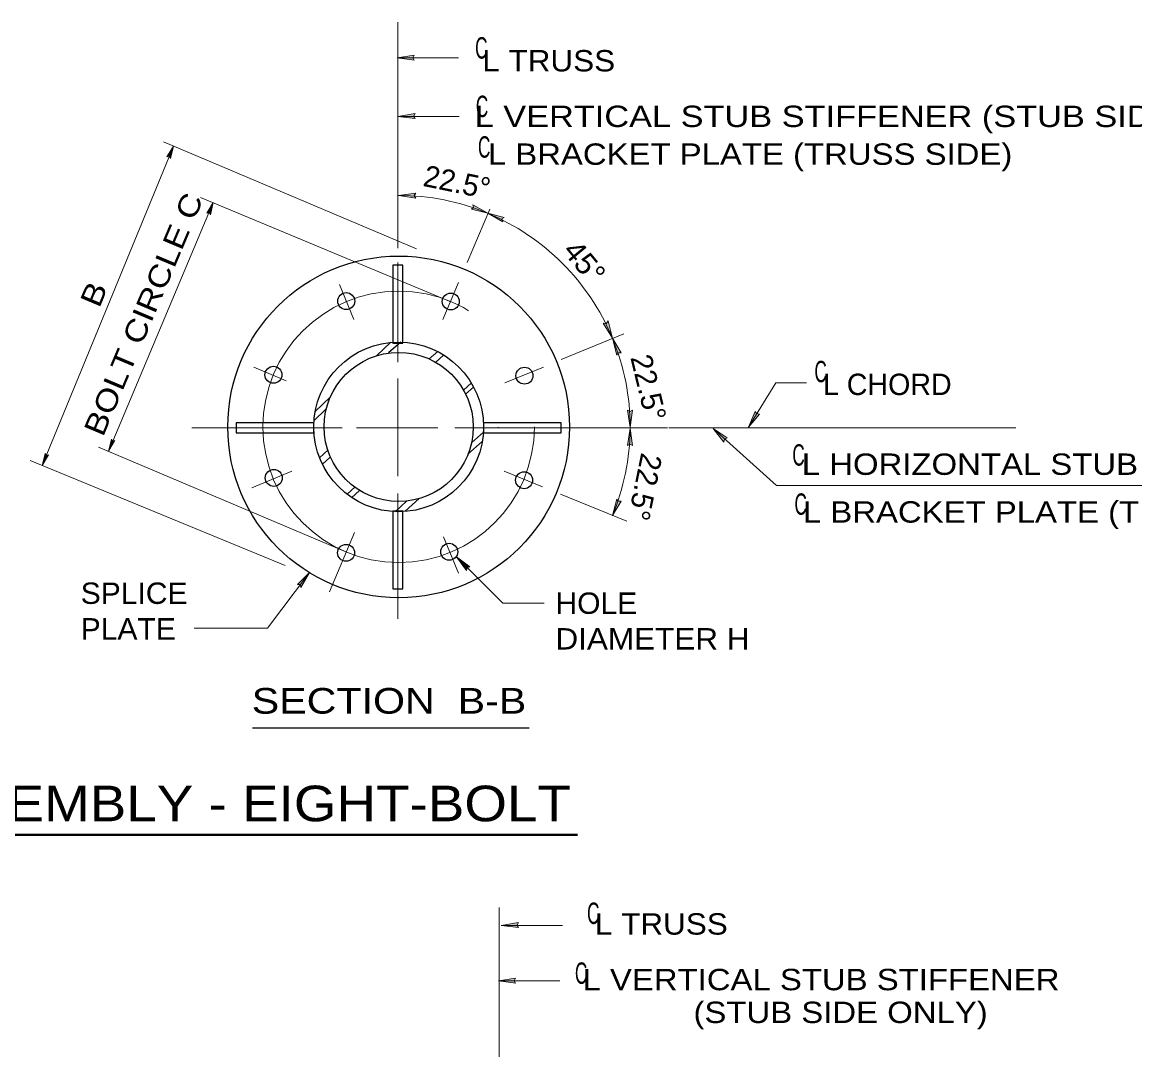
# Model space of a CAD drawing. Extents: x 312601.858 to 312602.699, y 144420.109 to 144420.704.
# Drawn here: x 312602.0748 to 312602.2309, y 144420.3443 to 144420.4884 of the extents above; entities that cross this region are included whole.
import ezdxf
from ezdxf.enums import TextEntityAlignment as Align

# ---------------------------------------------------------------- set-up
doc = ezdxf.new("R2010")
doc.units = 0
doc.header["$LTSCALE"] = 0.0012
doc.linetypes.add('DOT_DASHED', pattern=[7.7, 5, -1.2, 0.3, -1.2])
for name, color, linetype, lineweight in [('1', 7, 'Continuous', 13), ('2', 7, 'Continuous', 25), ('39', 7, 'Continuous', 13)]:
    doc.layers.add(name, color=color, linetype=linetype, lineweight=lineweight)

msp = doc.modelspace()

# ---------------------------------------------------------------- hatches: boundary and pattern name
at = {"layer": '39'}
for points in [[(312602.1296, 144420.4834), (312602.1298, 144420.4831), (312602.1274, 144420.4834), (312602.1298, 144420.4838)], [(312602.1297, 144420.4752), (312602.1299, 144420.4749), (312602.1275, 144420.4752), (312602.1299, 144420.4756)], [(312602.0954, 144420.4696), (312602.0951, 144420.4695), (312602.096, 144420.471), (312602.0956, 144420.4693)], [(312602.1298, 144420.4641), (312602.13, 144420.4637), (312602.1276, 144420.4641), (312602.13, 144420.4644)], [(312602.1298, 144420.4641), (312602.13, 144420.4637), (312602.1276, 144420.4641), (312602.13, 144420.4644)], [(312602.101, 144420.4617), (312602.1007, 144420.4616), (312602.1016, 144420.4631), (312602.1012, 144420.4614)], [(312602.1381, 144420.4624), (312602.138, 144420.4628), (312602.1401, 144420.4616), (312602.1378, 144420.4622)], [(312602.1381, 144420.4624), (312602.138, 144420.4628), (312602.1401, 144420.4616), (312602.1378, 144420.4622)], [(312602.1421, 144420.4608), (312602.1422, 144420.4604), (312602.1401, 144420.4616), (312602.1424, 144420.461)], [(312602.1421, 144420.4608), (312602.1422, 144420.4604), (312602.1401, 144420.4616), (312602.1424, 144420.461)], [(312602.1567, 144420.4461), (312602.157, 144420.4465), (312602.1576, 144420.4441), (312602.1563, 144420.4462)], [(312602.1584, 144420.442), (312602.1582, 144420.4417), (312602.1576, 144420.4441), (312602.1588, 144420.442)], [(312602.1584, 144420.442), (312602.1582, 144420.4417), (312602.1576, 144420.4441), (312602.1588, 144420.442)], [(312602.1601, 144420.4338), (312602.1604, 144420.434), (312602.1601, 144420.4316), (312602.1597, 144420.434)], [(312602.1601, 144420.4338), (312602.1604, 144420.434), (312602.1601, 144420.4316), (312602.1597, 144420.434)], [(312602.1778, 144420.4335), (312602.1782, 144420.4334), (312602.1767, 144420.4316), (312602.1776, 144420.4338)], [(312602.1778, 144420.4335), (312602.1782, 144420.4334), (312602.1767, 144420.4316), (312602.1776, 144420.4338)], [(312602.1601, 144420.4292), (312602.1597, 144420.429), (312602.1601, 144420.4314), (312602.1604, 144420.429)], [(312602.1601, 144420.4292), (312602.1597, 144420.429), (312602.1601, 144420.4314), (312602.1604, 144420.429)], [(312602.1733, 144420.4299), (312602.1732, 144420.4295), (312602.1717, 144420.4314), (312602.1737, 144420.4301)], [(312602.0875, 144420.4296), (312602.0878, 144420.4297), (312602.0869, 144420.4282), (312602.0873, 144420.4299)], [(312602.0782, 144420.4276), (312602.0785, 144420.4277), (312602.0776, 144420.4262), (312602.078, 144420.4279)], [(312602.1584, 144420.4212), (312602.1588, 144420.4212), (312602.1576, 144420.4192), (312602.1582, 144420.4215)], [(312602.1584, 144420.4212), (312602.1588, 144420.4212), (312602.1576, 144420.4192), (312602.1582, 144420.4215)], [(312602.1372, 144420.4119), (312602.1371, 144420.4115), (312602.1357, 144420.4134), (312602.1376, 144420.412)], [(312602.1138, 144420.4095), (312602.1134, 144420.4095), (312602.1151, 144420.4112), (312602.1139, 144420.4091)], [(312602.1442, 144420.3617), (312602.1444, 144420.3614), (312602.142, 144420.3617), (312602.1444, 144420.3621)], [(312602.1438, 144420.3539), (312602.144, 144420.3536), (312602.1416, 144420.3539), (312602.144, 144420.3543)]]:
    msp.add_hatch(color=256, dxfattribs=at).paths.add_polyline_path(points)

# ---------------------------------------------------------------- linework, layer by layer
at = {"layer": '1'}
for p, q in [((312602.1275, 144420.4884), (312602.1275, 144420.4567)), ((312602.1274, 144420.4834), (312602.136, 144420.4834)), ((312602.1275, 144420.4752), (312602.1361, 144420.4752)), ((312602.0776, 144420.4262), (312602.096, 144420.471)), ((312602.1301, 144420.4566), (312602.0946, 144420.4716)), ((312602.0869, 144420.4282), (312602.1016, 144420.4631)), ((312602.1349, 144420.4492), (312602.0998, 144420.4638)), ((312602.1404, 144420.4622), (312602.1372, 144420.4547)), ((312602.1592, 144420.4447), (312602.1504, 144420.4411)), ((312602.1275, 144420.4384), (312602.1275, 144420.4247)), ((312602.1217, 144420.4315), (312602.1331, 144420.4315)), ((312602.1655, 144420.4315), (312602.2142, 144420.4315)), ((312602.1806, 144420.4234), (312602.1717, 144420.4314)), ((312602.1202, 144420.4141), (312602.0855, 144420.4288)), ((312602.1117, 144420.4122), (312602.0759, 144420.4269)), ((312602.1503, 144420.4222), (312602.1596, 144420.4184)), ((312602.288, 144420.4234), (312602.1806, 144420.4234)), ((312602.1417, 144420.3312), (312602.1417, 144420.3642)), ((312602.142, 144420.3617), (312602.1506, 144420.3617)), ((312602.1416, 144420.3539), (312602.1502, 144420.3539))]:
    msp.add_line(p, q, dxfattribs=at)
at = {"layer": '1', "linetype": 'DOT_DASHED'}
for p, q in [((312602.1275, 144420.4547), (312602.1275, 144420.4407)), ((312602.136, 144420.4519), (312602.1338, 144420.4467)), ((312602.1193, 144420.4516), (312602.1213, 144420.4467)), ((312602.1073, 144420.44), (312602.1118, 144420.4381)), ((312602.1479, 144420.44), (312602.1425, 144420.4378)), ((312602.0986, 144420.4315), (312602.1197, 144420.4315)), ((312602.1355, 144420.4315), (312602.1653, 144420.4315)), ((312602.1126, 144420.4254), (312602.107, 144420.4231)), ((312602.1424, 144420.4254), (312602.1478, 144420.4232)), ((312602.1275, 144420.4223), (312602.1275, 144420.4047)), ((312602.1214, 144420.4168), (312602.1179, 144420.4085)), ((312602.1339, 144420.4162), (312602.136, 144420.4111))]:
    msp.add_line(p, q, dxfattribs=at)
at = {"layer": '1', "lineweight": 40}
msp.add_line((312601.9976, 144420.3744), (312602.1527, 144420.3744), dxfattribs=at)
at = {"layer": '1'}
msp.add_lwpolyline([(312602.1848, 144420.4378), (312602.1805, 144420.4378), (312602.1767, 144420.4316)], dxfattribs=at)
at = {"layer": '1', "lineweight": 25}
for centre, radius in [((312602.127605, 144420.43163), 0.02397), ((312602.120247, 144420.449276), 0.00119), ((312602.134915, 144420.449225), 0.00119), ((312602.127605, 144420.43163), 0.0119), ((312602.127605, 144420.43163), 0.010455), ((312602.11004, 144420.43894), 0.00119), ((312602.145251, 144420.438818), 0.00119), ((312602.110089, 144420.424472), 0.00119), ((312602.1452, 144420.42415), 0.00119), ((312602.120225, 144420.413965), 0.00119), ((312602.134693, 144420.414114), 0.00119)]:
    msp.add_circle(centre, radius, dxfattribs=at)
at = {"layer": '1', "linetype": 'DOT_DASHED'}
msp.add_circle((312602.127605, 144420.43163), 0.01904, dxfattribs=at)
at = {"layer": '1'}
for start, end in [(67.38432, 89.99981), (22.64326, 67.38432), (359.9471, 22.49295), (337.41067, 359.59571)]:
    msp.add_arc((312602.127605, 144420.43163), 0.03247, start, end, dxfattribs=at)
at = {"layer": '2'}
for p, q in [((312602.1245, 144420.4416), (312602.1265, 144420.4435)), ((312602.1279, 144420.4435), (312602.1262, 144420.442)), ((312602.1071, 144420.3894), (312602.1459, 144420.3894))]:
    msp.add_line(p, q, dxfattribs=at)
at = {"layer": '2', "lineweight": 13}
for p, q in [((312602.1319, 144420.4412), (312602.1331, 144420.4422)), ((312602.1328, 144420.4407), (312602.1339, 144420.4417)), ((312602.1367, 144420.4368), (312602.1378, 144420.4378)), ((312602.137, 144420.4362), (312602.1381, 144420.4372)), ((312602.1159, 144420.4338), (312602.118, 144420.4358)), ((312602.1157, 144420.4325), (312602.1174, 144420.4341)), ((312602.1415, 144420.4315), (312602.1416, 144420.4316)), ((312602.1378, 144420.4294), (312602.1395, 144420.4309)), ((312602.1165, 144420.4273), (312602.1177, 144420.4284)), ((312602.1373, 144420.4278), (312602.1393, 144420.4296)), ((312602.1169, 144420.4264), (312602.118, 144420.4274)), ((312602.1204, 144420.4222), (312602.1215, 144420.4232)), ((312602.121, 144420.4217), (312602.1221, 144420.4227)), ((312602.1271, 144420.4197), (312602.1287, 144420.4212)), ((312602.1285, 144420.4198), (312602.1305, 144420.4216))]:
    msp.add_line(p, q, dxfattribs=at)
at = {"layer": '2'}
for points in [[(312602.1268, 144420.4434), (312602.1282, 144420.4434), (312602.1282, 144420.4543), (312602.1268, 144420.4543)], [(312602.1157, 144420.4308), (312602.1157, 144420.4322), (312602.1048, 144420.4322), (312602.1048, 144420.4308)], [(312602.1504, 144420.4308), (312602.1504, 144420.4322), (312602.1395, 144420.4322), (312602.1395, 144420.4308)], [(312602.1268, 144420.4089), (312602.1282, 144420.4089), (312602.1282, 144420.4198), (312602.1268, 144420.4198)]]:
    msp.add_lwpolyline(points, close=True, dxfattribs=at)
at = {"layer": '2', "lineweight": 13}
for points in [[(312602.1357, 144420.4134), (312602.1422, 144420.4069), (312602.148, 144420.4069)], [(312602.0989, 144420.4034), (312602.1092, 144420.4034), (312602.1151, 144420.4112)]]:
    msp.add_lwpolyline(points, dxfattribs=at)
at = {"layer": '39'}
for points in [[(312602.1296, 144420.4834), (312602.1298, 144420.4831), (312602.1274, 144420.4834), (312602.1298, 144420.4838)], [(312602.1297, 144420.4752), (312602.1299, 144420.4749), (312602.1275, 144420.4752), (312602.1299, 144420.4756)], [(312602.0954, 144420.4696), (312602.0951, 144420.4695), (312602.096, 144420.471), (312602.0956, 144420.4693)], [(312602.1298, 144420.4641), (312602.13, 144420.4637), (312602.1276, 144420.4641), (312602.13, 144420.4644)], [(312602.1298, 144420.4641), (312602.13, 144420.4637), (312602.1276, 144420.4641), (312602.13, 144420.4644)], [(312602.101, 144420.4617), (312602.1007, 144420.4616), (312602.1016, 144420.4631), (312602.1012, 144420.4614)], [(312602.1381, 144420.4624), (312602.138, 144420.4628), (312602.1401, 144420.4616), (312602.1378, 144420.4622)], [(312602.1381, 144420.4624), (312602.138, 144420.4628), (312602.1401, 144420.4616), (312602.1378, 144420.4622)], [(312602.1421, 144420.4608), (312602.1422, 144420.4604), (312602.1401, 144420.4616), (312602.1424, 144420.461)], [(312602.1421, 144420.4608), (312602.1422, 144420.4604), (312602.1401, 144420.4616), (312602.1424, 144420.461)], [(312602.1567, 144420.4461), (312602.157, 144420.4465), (312602.1576, 144420.4441), (312602.1563, 144420.4462)], [(312602.1584, 144420.442), (312602.1582, 144420.4417), (312602.1576, 144420.4441), (312602.1588, 144420.442)], [(312602.1584, 144420.442), (312602.1582, 144420.4417), (312602.1576, 144420.4441), (312602.1588, 144420.442)], [(312602.1601, 144420.4338), (312602.1604, 144420.434), (312602.1601, 144420.4316), (312602.1597, 144420.434)], [(312602.1601, 144420.4338), (312602.1604, 144420.434), (312602.1601, 144420.4316), (312602.1597, 144420.434)], [(312602.1778, 144420.4335), (312602.1782, 144420.4334), (312602.1767, 144420.4316), (312602.1776, 144420.4338)], [(312602.1778, 144420.4335), (312602.1782, 144420.4334), (312602.1767, 144420.4316), (312602.1776, 144420.4338)], [(312602.1601, 144420.4292), (312602.1597, 144420.429), (312602.1601, 144420.4314), (312602.1604, 144420.429)], [(312602.1601, 144420.4292), (312602.1597, 144420.429), (312602.1601, 144420.4314), (312602.1604, 144420.429)], [(312602.1733, 144420.4299), (312602.1732, 144420.4295), (312602.1717, 144420.4314), (312602.1737, 144420.4301)], [(312602.0875, 144420.4296), (312602.0878, 144420.4297), (312602.0869, 144420.4282), (312602.0873, 144420.4299)], [(312602.0782, 144420.4276), (312602.0785, 144420.4277), (312602.0776, 144420.4262), (312602.078, 144420.4279)], [(312602.1584, 144420.4212), (312602.1588, 144420.4212), (312602.1576, 144420.4192), (312602.1582, 144420.4215)], [(312602.1584, 144420.4212), (312602.1588, 144420.4212), (312602.1576, 144420.4192), (312602.1582, 144420.4215)], [(312602.1372, 144420.4119), (312602.1371, 144420.4115), (312602.1357, 144420.4134), (312602.1376, 144420.412)], [(312602.1138, 144420.4095), (312602.1134, 144420.4095), (312602.1151, 144420.4112), (312602.1139, 144420.4091)], [(312602.1442, 144420.3617), (312602.1444, 144420.3614), (312602.142, 144420.3617), (312602.1444, 144420.3621)], [(312602.1438, 144420.3539), (312602.144, 144420.3536), (312602.1416, 144420.3539), (312602.144, 144420.3543)]]:
    msp.add_lwpolyline(points, close=True, dxfattribs=at)

# ---------------------------------------------------------------- texts
at = {"layer": '2'}
for s, height, width, p in [('C', 0.003, 0.6, (312602.1392, 144420.4833)), ('L TRUSS', 0.003, 1.1, (312602.14865, 144420.4815)), ('C', 0.003, 0.6, (312602.1393, 144420.4751)), ('L VERTICAL STUB STIFFENER (STUB SIDE)', 0.003, 1.2, (312602.18815, 144420.4737)), ('C', 0.003, 0.6, (312602.1396, 144420.4694)), ('L BRACKET PLATE (TRUSS SIDE)', 0.003, 1.15, (312602.1769, 144420.4684)), ('C', 0.003, 0.6, (312602.1868, 144420.4379)), ('C', 0.003, 0.6, (312602.1837, 144420.4262)), ('L HORIZONTAL STUB STIFFENER (STUB SIDE)', 0.003, 1.15, (312602.23555, 144420.4249)), ('C', 0.003, 0.6, (312602.184, 144420.4193)), ('L BRACKET PLATE (TRUSS SIDE)', 0.003, 1.15, (312602.2211, 144420.4182)), ('SECTION  B-B', 0.0036, 1.2, (312602.12625, 144420.3914)), ('CHORD SPLICE ASSEMBLY - EIGHT-BOLT', 0.005, 1.15, (312602.07465, 144420.3763)), ('C', 0.003, 0.6, (312602.1549, 144420.3619)), ('L TRUSS', 0.003, 1.1, (312602.16445, 144420.3604)), ('C', 0.003, 0.6, (312602.1532, 144420.3535)), ('L VERTICAL STUB STIFFENER', 0.003, 1.15, (312602.18685, 144420.3526)), ('(STUB SIDE ONLY)', 0.003, 1.15, (312602.1896, 144420.348))]:
    msp.add_text(s, height=height, dxfattribs=dict(at, width=width)).set_placement(p, align=Align.CENTER)
for height, rotation, p in [(0.003, 348.362, (312602.135497, 144420.464506)), (0.002999, 283.526, (312602.161195, 144420.436801)), (0.003, 258.431, (312602.160713, 144420.423501))]:
    msp.add_text('22.5°', height=height, rotation=rotation, dxfattribs=at).set_placement(p, align=Align.CENTER)
for s, height, rotation, width, p in [('BOLT CIRCLE C', 0.003, 67.123, 1.2, (312602.09319, 144420.446867)), ('45°', 0.002999, 309.608, 1.05, (312602.152526, 144420.453806)), ('B', 0.003, 67.123, 1.2, (312602.086219, 144420.449667))]:
    msp.add_text(s, height=height, rotation=rotation, dxfattribs=dict(at, width=width)).set_placement(p, align=Align.CENTER)
msp.add_text('L CHORD', height=0.003, dxfattribs=at).set_placement((312602.19615, 144420.4361), align=Align.CENTER)
for s, width, p in [('SPLICE', 1.05, (312602.083, 144420.4068)), ('HOLE ', 1.05, (312602.1496, 144420.4054)), ('PLATE', 1.05, (312602.083, 144420.4018)), ('DIAMETER H', 1.1, (312602.1496, 144420.4004))]:
    msp.add_text(s, height=0.003, dxfattribs=dict(at, width=width)).set_placement(p)

doc.saveas('drawing.dxf')
